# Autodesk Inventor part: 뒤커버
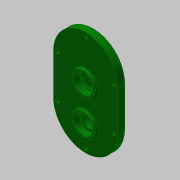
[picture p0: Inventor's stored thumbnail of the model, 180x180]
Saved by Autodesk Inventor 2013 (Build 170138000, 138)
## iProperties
Created: 2016-12
Part Number: 뒤커버
Material: 알루미늄 6061
Document SubType Name: Modeling
Designer: mduedu
Density: 2.71 g/cm^3
Mass: 236.429 g
Surface Area: 240.702 cm^2
Volume: 87.2433 cm^3
Author: mduedu
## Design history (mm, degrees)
sketch "스케치1"
  geometry: L1 (40, -25)-(40, 25); L2 (-40, 25)-(-40, -25); L3 (-40, -25)-(40, 25); L4 (40, -25)-(-40, 25); A1 r 40 centre (0, 25) between (40, 25) and (-40, 25); A2 r 40 centre (0, -25) between (-40, -25) and (40, -25); 1 further point
  constraints: 8 end point, 4 point on circle, 4 tangent, 2 centre point, 2 midpoint, 1 parallel, 1 vertical
  dimensions: "d0" = 130 dimension on A2 A1; "d2" = 80 distance between parallel lines of L1 L2
extrude "돌출1" new body sketch "스케치1" distance "d3" = 10; taper "d4" = 0 deg
sketch "스케치2"
  geometry: C1 r 14 at (0, 11); 1 further point
  constraints: 1 centre point, 1 vertical alignment
  dimensions: "d5" = 28 diameter of C1; "d6" = 11 distance of C1.centre point (0, 0)
extrude "돌출2" join sketch "스케치2" distance "d7" = 3; taper "d8" = 0 deg
sketch "스케치3"
  geometry: C1 r 14 at (0, -33.1); C2 r 14 at (0, 11) reference; 1 further point
  constraints: 1 centre point, 1 vertical alignment
  dimensions: "d9" = 28 diameter of C1; "d69" = 44.1 distance of C1.centre C2.centre
extrude "돌출3" join sketch "스케치3" distance "d11" = 3; taper "d12" = 0 deg
hole "구멍1" diameter "d15" = 22; stored, may be unused: countersink angle "d19" = 90 deg, drill point angle "d21" = 0 deg; dims "d13" = 10, "d14" = 10, "d16" = 6, "d17" = 4, "d18" = 2, "d20" = 7
hole "구멍2" diameter "d24" = 18; stored, may be unused: countersink angle "d28" = 90 deg, drill point angle "d30" = 0 deg; dims "d22" = 10, "d23" = 10, "d25" = 6, "d26" = 4, "d27" = 2, "d29" = 1
hole "구멍3" diameter "d33" = 22; stored, may be unused: countersink angle "d37" = 90 deg, drill point angle "d39" = 0 deg; dims "d31" = 10, "d32" = 10, "d34" = 6, "d35" = 4, "d36" = 2, "d38" = 7
sketch "스케치4"
  geometry: C1 r 14 at (0, -33.1) reference; C2 r 18 at (0, -33.1); 1 further point
  constraints: 1 centre point, 1 coincident
  dimensions: "d40" = 36 diameter of C2
extrude "돌출4" join sketch "스케치4" distance "d41" = 4; taper "d42" = 0 deg
hole "구멍4" diameter "d45" = 22; stored, may be unused: countersink angle "d49" = 90 deg, drill point angle "d51" = 0 deg; dims "d43" = 10, "d44" = 10, "d46" = 6, "d47" = 4, "d48" = 2, "d50" = 7
hole "구멍5" diameter "d54" = 15; stored, may be unused: countersink angle "d58" = 90 deg, drill point angle "d60" = 0 deg; dims "d52" = 10, "d53" = 10, "d55" = 6, "d56" = 4, "d57" = 2, "d59" = 7
fillet "모깎기1" dims "d61" = 0.3
fillet "모깎기2" dims "d62" = 2
chamfer "모따기1" distance "d63" = 1; stored, may be unused: second distance "d64" = 2, angle "d65" = 45 deg
fillet "모깎기3" dims "d66" = 2
fillet "모깎기4" dims "d67" = 2
fillet "모깎기5" dims "d68" = 2
sketch "스케치5"
  geometry: L1 (-40, 25)-(-40, -25) reference; L2 (40, -25)-(40, 25) reference; L3 (35, 25)-(35, -25); L4 (-35, -25)-(-35, 25); A1 r 40 centre (0, 25) between (40, 25) and (-40, 25) reference; A2 r 40 centre (0, -25) between (-40, -25) and (40, -25) reference; A3 r 35 centre (0, 25) between (35, 25) and (-35, 25); A4 r 35 centre (0, -25) between (-35, -25) and (35, -25); 2 further points
  constraints: 5 point on circle, 4 end point, 2 centre point, 1 vertical alignment, 3 other
  dimensions: "d70" = 5 distance between parallel lines of L2 L3
sketch "스케치6"
  geometry: 1 further point
hole "구멍6" sketch "스케치6" at (0, 60) diameter "d71" = 4.5; stored, may be unused: countersink angle "d75" = 90 deg, drill point angle "d77" = 0 deg; dims "d72" = 6, "d73" = 8, "d74" = 4.6, "d76" = 8
node "솔리드1"
pattern_linear "직사각형 패턴1"
